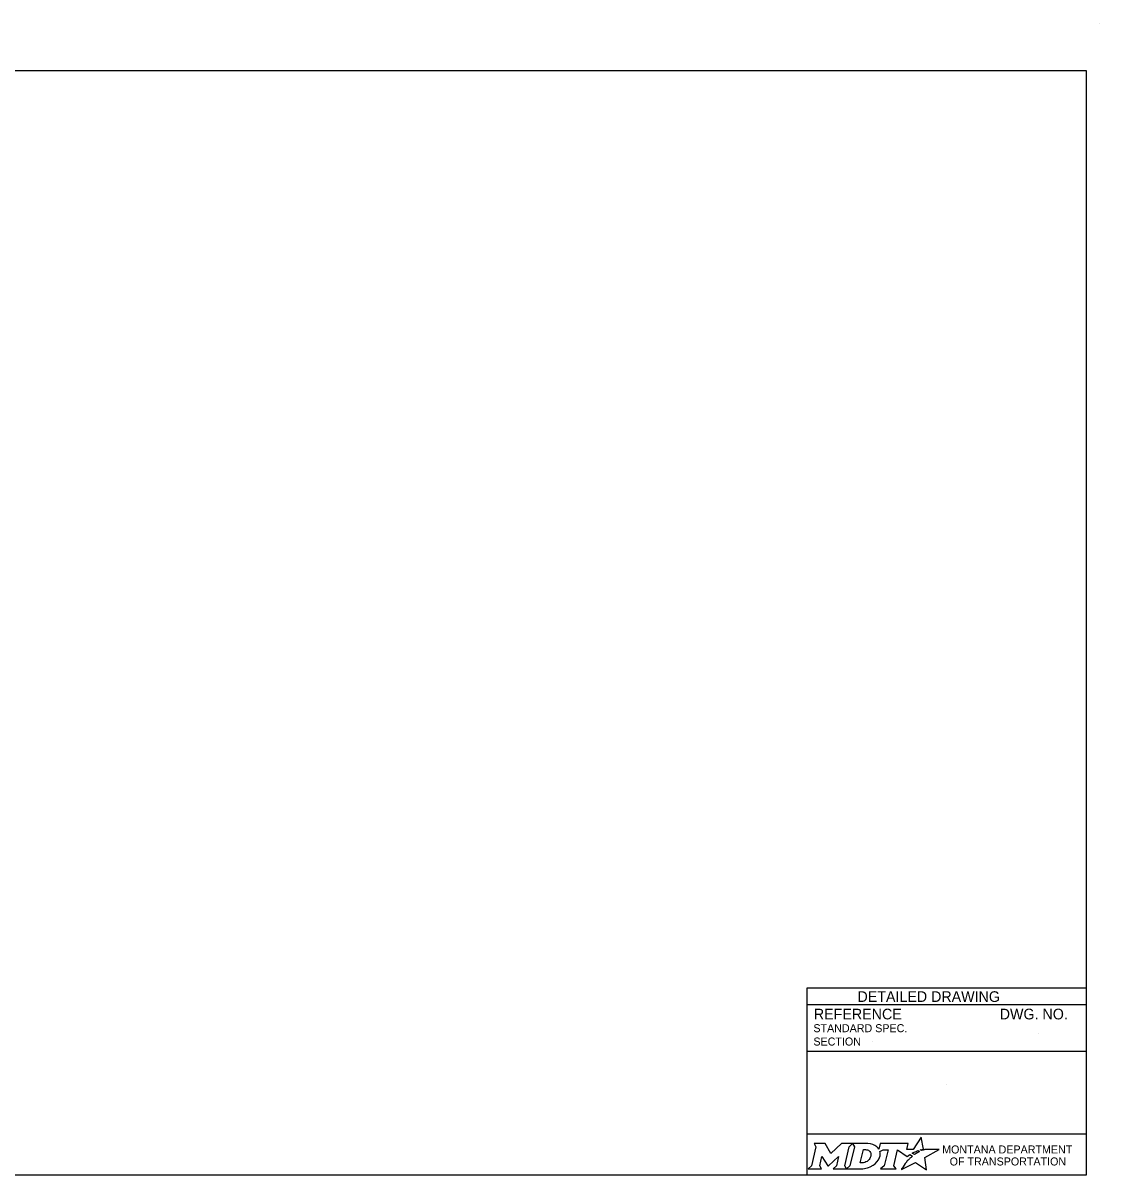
# Model space of a CAD drawing. Extents: x 49991.4 to 50021, y 49987.6 to 50011.4.
# Drawn here: x 50012.96 to 50021.04, y 49999.89 to 50008.52 of the extents above; entities that cross this region are included whole.
import ezdxf

# ---------------------------------------------------------------- set-up
doc = ezdxf.new("R2010")
doc.units = 0
for name, color, linetype in [('Default', 7, 'Continuous'), ('Level 1', 7, 'Continuous'), ('Level 4', 7, 'Continuous')]:
    doc.layers.add(name, color=color, linetype=linetype)

msp = doc.modelspace()

# ---------------------------------------------------------------- linework, layer by layer
at = {"layer": 'Default'}
for points in [[(50018.8933, 50000.1206), (50018.9074, 50000.0972), (50018.8739, 49999.9539), (50018.8482, 49999.9314), (50018.9498, 49999.9314), (50018.9363, 49999.9542), (50018.9525, 50000.0243), (50018.9962, 49999.9553), (50019.0015, 49999.9553), (50019.0766, 50000.0248), (50019.0602, 49999.9537), (50019.0355, 49999.9317), (50019.1371, 49999.9317), (50019.1233, 49999.955), (50019.1565, 50000.0974)], [(50019.1565, 50000.0974), (50019.1818, 50000.1206), (50019.0994, 50000.1206), (50019.0198, 50000.0476), (50018.9753, 50000.1203), (50018.8933, 50000.1206)], [(50019.2954, 50000.1206), (50019.1818, 50000.1206), (50019.1965, 50000.0977), (50019.1626, 49999.9539), (50019.1371, 49999.9317), (50019.2477, 49999.9317)], [(50019.7003, 50000.0679), (50019.69, 50000.0735), (50019.7016, 50000.0763), (50019.7132, 50000.0783), (50019.6958, 50000.1684), (50019.6363, 50000.0771), (50019.589, 50000.0764), (50019.5993, 50000.1205), (50019.3901, 50000.1206), (50019.38, 50000.0781), (50019.3742, 50000.0864)], [(50019.3194, 50000.0339), (50019.3182, 50000.0258), (50019.315, 50000.0165), (50019.3108, 50000.0083), (50019.3052, 50000.0008), (50019.2987, 49999.9939), (50019.2908, 49999.9876), (50019.2825, 49999.9829), (50019.2734, 49999.979), (50019.2643, 49999.9767), (50019.2551, 49999.9758), (50019.2392, 49999.9758), (50019.2628, 50000.0758), (50019.2788, 50000.0758), (50019.2864, 50000.0752), (50019.294, 50000.0733), (50019.3006, 50000.0703), (50019.3067, 50000.0661), (50019.3115, 50000.0611), (50019.3152, 50000.0551), (50019.3179, 50000.0489), (50019.3195, 50000.0415), (50019.3195, 50000.0385), (50019.3194, 50000.0339)], [(50019.3868, 50000.0615), (50019.4114, 50000.0746), (50019.4483, 50000.0746), (50019.4197, 49999.9541), (50019.3922, 49999.9314), (50019.5084, 49999.9314), (50019.4914, 49999.9543), (50019.5196, 50000.0745), (50019.5909, 50000.0228), (50019.612, 50000.0379), (50019.6317, 50000.027)], [(50019.5759, 49999.9711), (50019.5606, 49999.9467), (50019.5559, 49999.9392), (50019.5501, 49999.9306), (50019.5478, 49999.9263), (50019.6531, 49999.9794), (50019.737, 49999.9243), (50019.7239, 50000.017), (50019.8308, 50000.0754), (50019.7815, 50000.0762), (50019.7514, 50000.0766), (50019.7306, 50000.0769), (50019.7238, 50000.0754), (50019.7189, 50000.0742), (50019.7105, 50000.0719), (50019.7003, 50000.0679)], [(50019.6499, 50000.0403), (50019.6475, 50000.0386), (50019.6292, 50000.0482), (50019.6395, 50000.0539), (50019.6436, 50000.0561), (50019.6522, 50000.0601), (50019.6579, 50000.0627), (50019.6658, 50000.0657), (50019.6731, 50000.0684), (50019.6849, 50000.061), (50019.6809, 50000.0589), (50019.6763, 50000.0564), (50019.6721, 50000.0542), (50019.6671, 50000.0513), (50019.6652, 50000.0502), (50019.6625, 50000.0486), (50019.66, 50000.0472), (50019.6577, 50000.0456), (50019.6551, 50000.0438), (50019.6524, 50000.042), (50019.6499, 50000.0403)], [(50019.2934, 49999.939), (50019.3018, 49999.9416), (50019.3148, 49999.947), (50019.3352, 49999.958)], [(50019.5898, 49999.9872), (50019.5898, 49999.9872)]]:
    msp.add_lwpolyline(points, dxfattribs=at)
for centre, radius, start, end in [((50019.3185, 50000.0422), 0.0709, 339.53292, 15.85821), ((50019.2745, 50000.0595), 0.1183, 300.91025, 339.13831)]:
    msp.add_arc(centre, radius, start, end, dxfattribs=at)
for centre, major_axis, ratio, start_param, end_param in [((50019.2933, 50000.0732), (0.0834, -0.0037), 0.568097, 0.61298, 1.570796), ((50019.3489, 50000.0805), (0.0361, -0.0295), 0.469099, 1.225588, 1.570796), ((50019.6206, 50000.0173), (-0.0112, -0.0097), 0.021651, 3.157348, 6.283185), ((50019.5829, 49999.9791), (-0.00694, -0.00806), 0.008222, 0, 3.137361), ((50019.5996, 49999.9974), (-0.0098, -0.0102), 0.016458, 3.141593, 6.279097), ((50019.248, 50000.08), (0, 0.1484), 0.987302, 3.139398, 3.456847)]:
    msp.add_ellipse(centre, major_axis=major_axis, ratio=ratio, start_param=start_param, end_param=end_param, dxfattribs=at)
at = {"layer": 'Level 1'}
msp.add_line((50021.0378, 50008.5236), (50021.0378, 50008.5236), dxfattribs=at)
msp.add_lwpolyline([(50020.9378, 50008.1646), (50009.7374, 50008.1646), (50009.7374, 49999.8856), (50020.9378, 49999.8856)], close=True, dxfattribs=at)
at = {"layer": 'Level 4'}
for p, q in [((50020.9378, 50001.2856), (50018.8378, 50001.2856)), ((50018.8378, 50001.2856), (50018.8378, 49999.8856)), ((50020.9378, 50001.1606), (50018.8378, 50001.1606)), ((50020.5739, 50000.9455), (50020.5739, 50000.9455)), ((50020.9378, 50000.8106), (50018.8378, 50000.8106)), ((50019.3321, 50000.8861), (50019.3321, 50000.8861)), ((50019.8878, 50000.5615), (50019.8878, 50000.5615)), ((50020.9378, 50000.1925), (50018.8378, 50000.1925))]:
    msp.add_line(p, q, dxfattribs=at)

# ---------------------------------------------------------------- texts
at = {"layer": 'Default'}
for s, p in [('MONTANA DEPARTMENT', (50019.854, 50000.0468)), ('OF TRANSPORTATION', (50019.9102, 49999.9568))]:
    msp.add_text(s, height=0.06, dxfattribs=at).set_placement(p)
at = {"layer": 'Level 4'}
for s, height, p in [('DETAILED DRAWING', 0.0799, (50019.2188, 50001.1831)), ('REFERENCE', 0.08, (50018.8914, 50001.0522)), ('DWG. NO.', 0.08, (50020.2856, 50001.0522)), ('STANDARD SPEC.', 0.06, (50018.8881, 50000.9562)), ('SECTION', 0.06, (50018.8881, 50000.8562))]:
    msp.add_text(s, height=height, dxfattribs=at).set_placement(p)

doc.saveas('drawing.dxf')
